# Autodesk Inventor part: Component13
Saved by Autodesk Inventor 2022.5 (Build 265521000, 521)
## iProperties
Created: 2024-12
Part Number: Component13
Material: Generic
Document SubType Name: Modeling
Designer: AdminForWorker
Density: 1 g/cm^3
Appearance: Default
Title: Component13
Author: AdminForWorker
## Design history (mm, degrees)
feature "Body2"
body "Solid1"
